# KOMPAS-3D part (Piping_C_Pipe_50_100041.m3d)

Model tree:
1. Plane XY
2. Plane ZX
3. Plane ZY
4. X Axis
5. Y Axis
6. Z Axis
7. Origin
8. Path  (labels: Тройник Dy 50; Труба Dy 50)
9. Plane of section
10. Section of pipe
11. Pipe
     Толщина стенки 1 = 1

Referenced files in C:\Program Files\ASCON\KOMPAS-3D V10\Libs\Piping\Models\Tanks\: Tanks.a3d
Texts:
  Pipe Dn 50
  Steel ASTM A295
  Three Point Plane
  Plane at Angle
  Line and Point Plane
  Axis through Two Vertices
  Axis of Feature
  Axis of Conical Surface
  Axis through Edge
  Приклеить элемент выдавливания
  Приклеить элемент вращения
  Приклеить кинематический элемент
  Приклеить элемент по сечениям
  Trim by Surface
  Trim by Sketch
  Feature with No History
  Intersection Axis of Two Planes
  Two Line Plane
  Line and Face Plane
  Bend by line
  Hole in sheet body
  Cut in sheet body
  Point in CM
  Linear Dimension from Line to Point
  Surface Finish Symbol
  Geometric Tolerance Symbol
  Текст на чертеже
  Линия-выноска #1
  Линия-выноска #2
  Линия-выноска #3
  Отклонения формы и база
  Марка координационной оси
  Марка/позиционное обозначение с линией-выноской
  Марка/позиционное обозначение на линии
  Марка/позиционное обозначение без линии-выноски
  Тройник Dy 50
  Труба Dy 50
